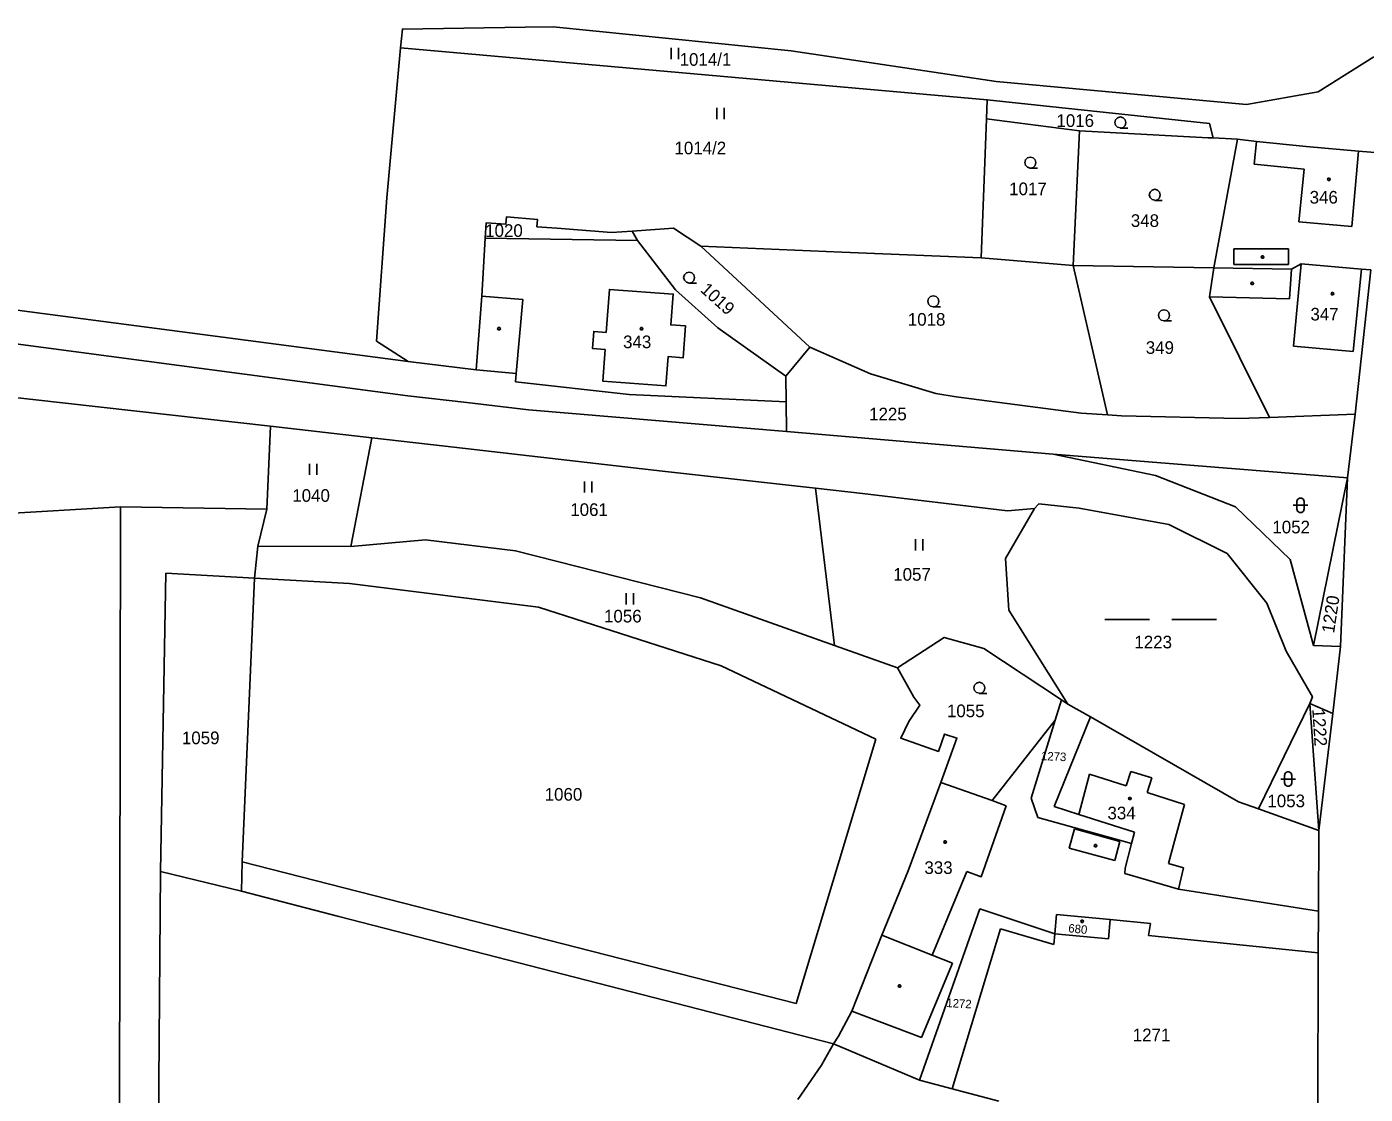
# Model space of a CAD drawing. Extents: x -812394 to -807601, y -1013097 to -1009266.
# Drawn here: x -811185.3 to -811005.4, y -1011291.2 to -1011147.8 of the extents above; entities that cross this region are included whole.
import ezdxf

# ---------------------------------------------------------------- set-up
doc = ezdxf.new("R2010")
doc.units = 0
for name, color, linetype in [('Default', 7, 'Continuous'), ('KN_HRANICE', 7, 'Continuous'), ('KN_KULTURY', 7, 'Continuous'), ('KN_PARCELY', 7, 'Continuous'), ('KN_SLUCKY', 7, 'Continuous')]:
    doc.layers.add(name, color=color, linetype=linetype)

# ---------------------------------------------------------------- blocks, each defined once
blk = doc.blocks.new('304')
at = {"layer": 'Default'}
blk.add_lwpolyline([(0, 0), (-0.38, 0.1), (-0.65, 0.37), (-0.75, 0.74), (-0.65, 1.11), (-0.38, 1.38), (-0.01, 1.48), (0.36, 1.38), (0.63, 1.11), (0.73, 0.73), (0.63, 0.35), (0.36, 0.08), (-0.02, -0.02), (0.98, -0.02)], dxfattribs=at)
blk = doc.blocks.new('306')
at = {"layer": 'Default'}
for p, q in [((-0.5, 1.5), (-0.5, 0)), ((0.5, 0), (0.5, 1.5))]:
    blk.add_line(p, q, dxfattribs=at)
blk = doc.blocks.new('316')
at = {"layer": 'Default'}
for points in [[(-0.5, 1.5), (-0.4, 1.79), (-0.15, 1.97), (0.16, 1.97), (0.41, 1.79), (0.51, 1.5), (0.51, 0.5), (0.41, 0.21), (0.16, 0.03), (-0.15, 0.03), (-0.4, 0.21), (-0.5, 0.5), (-0.5, 1.5)], [(-1, 1), (0.27, 1), (1, 1)]]:
    blk.add_lwpolyline(points, dxfattribs=at)
blk = doc.blocks.new('803')
at = {"layer": 'Default'}
for p, q in [((-7.5, 0), (-1.5, 0)), ((1.5, 0), (7.5, 0))]:
    blk.add_line(p, q, dxfattribs=at)
blk = doc.blocks.new('402')
at = {"layer": 'Default'}
blk.add_lwpolyline([(0.09, 0.15), (0.18, 0), (0.09, -0.15), (-0.09, -0.15), (-0.18, 0), (-0.09, 0.15), (0.09, 0.15)], dxfattribs=at)

msp = doc.modelspace()

# ---------------------------------------------------------------- linework, layer by layer
at = {"layer": 'KN_HRANICE'}
for p, q in [((-811114.53, -1011147.8), (-811118.29, -1011147.86)), ((-811082.55, -1011151.04), (-811114.53, -1011147.8)), ((-811135.05, -1011150.61), (-811056.18, -1011157.62)), ((-811055, -1011155.17), (-811082.55, -1011151.04)), ((-811004.2, -1011151.86), (-811011.7, -1011156.55)), ((-811021.36, -1011158.23), (-811055, -1011155.17)), ((-811011.7, -1011156.55), (-811021.36, -1011158.23)), ((-811056.28, -1011160.19), (-811056.18, -1011157.62)), ((-811056.99, -1011178.87), (-811056.28, -1011160.19)), ((-811056.28, -1011160.19), (-811043.79, -1011161.8)), ((-811043.79, -1011161.8), (-811044.65, -1011179.88)), ((-811026.5, -1011162.71), (-811043.79, -1011161.8)), ((-811025.83, -1011162.74), (-811026.5, -1011162.71)), ((-811022.54, -1011162.91), (-811025.83, -1011162.74)), ((-811022.54, -1011162.91), (-811025.73, -1011180.21)), ((-811020, -1011163.23), (-811022.54, -1011162.91)), ((-811013.31, -1011163.87), (-811020, -1011163.23)), ((-811006.28, -1011164.5), (-811013.31, -1011163.87)), ((-811002.95, -1011164.79), (-811006.28, -1011164.5)), ((-811124.13, -1011184), (-811123.68, -1011176.2)), ((-811123.68, -1011176.2), (-811103.23, -1011176.54)), ((-811103.94, -1011175.27), (-811098.37, -1011174.88)), ((-811103.94, -1011175.27), (-811103.23, -1011176.54)), ((-811098.37, -1011174.88), (-811094.68, -1011177.27)), ((-811080.02, -1011190.85), (-811094.68, -1011177.27)), ((-811056.99, -1011178.87), (-811044.65, -1011179.88)), ((-811044.65, -1011179.88), (-811025.73, -1011180.21)), ((-811044.65, -1011179.88), (-811040.04, -1011199.96)), ((-811015.31, -1011180.39), (-811013.97, -1011179.67)), ((-811005.89, -1011180.37), (-811013.97, -1011179.67)), ((-811025.73, -1011180.21), (-811026.32, -1011184.09)), ((-811025.73, -1011180.21), (-811015.31, -1011180.39)), ((-811006.73, -1011199.88), (-811004.64, -1011180.47)), ((-811005.89, -1011180.37), (-811004.64, -1011180.47)), ((-811134.04, -1011192.78), (-811204.59, -1011183.52)), ((-811124.88, -1011193.92), (-811124.13, -1011184)), ((-811026.32, -1011184.09), (-811018.25, -1011200.3)), ((-811080.02, -1011190.85), (-811083.26, -1011194.74)), ((-811134.04, -1011192.78), (-811124.88, -1011193.92)), ((-811119.51, -1011194.4), (-811124.88, -1011193.92)), ((-811119.59, -1011195.52), (-811119.51, -1011194.4)), ((-811210.26, -1011194.98), (-811152.56, -1011201.49)), ((-811083.26, -1011194.74), (-811083.23, -1011198.18)), ((-811126.17, -1011198.3), (-811117.85, -1011199.26)), ((-811117.85, -1011199.26), (-811083.19, -1011202.2)), ((-811083.23, -1011198.18), (-811083.19, -1011202.2)), ((-811153.06, -1011212.61), (-811152.56, -1011201.49)), ((-811152.56, -1011201.49), (-811138.94, -1011203.04)), ((-811040.04, -1011199.96), (-811038.15, -1011200.07)), ((-811038.15, -1011200.07), (-811022.4, -1011200.45)), ((-811018.25, -1011200.3), (-811022.4, -1011200.45)), ((-811006.73, -1011199.88), (-811018.25, -1011200.3)), ((-811006.73, -1011199.88), (-811007.74, -1011208.42)), ((-811141.76, -1011217.63), (-811138.94, -1011203.04)), ((-811138.94, -1011203.04), (-811129.08, -1011204.17)), ((-811083.19, -1011202.2), (-811047.34, -1011205.25)), ((-811129.08, -1011204.17), (-811099.83, -1011207.51)), ((-811047.34, -1011205.25), (-811007.74, -1011208.42)), ((-811099.83, -1011207.51), (-811079.29, -1011209.81)), ((-811012.31, -1011230.97), (-811007.74, -1011208.42)), ((-811007.74, -1011208.42), (-811008.72, -1011231.09)), ((-811076.71, -1011230.96), (-811079.29, -1011209.81)), ((-811192.07, -1011213.48), (-811172.71, -1011212.32)), ((-811172.71, -1011212.32), (-811172.89, -1011326.55)), ((-811153.06, -1011212.61), (-811172.71, -1011212.32)), ((-811154.23, -1011217.6), (-811153.06, -1011212.61)), ((-811154.72, -1011221.9), (-811154.23, -1011217.6)), ((-811141.76, -1011217.63), (-811154.23, -1011217.6)), ((-811167.33, -1011261.3), (-811166.6, -1011221.24)), ((-811166.6, -1011221.24), (-811154.72, -1011221.9)), ((-811154.72, -1011221.9), (-811156.36, -1011260.04)), ((-811154.72, -1011221.9), (-811141.93, -1011222.61)), ((-811141.93, -1011222.61), (-811116.52, -1011225.79)), ((-811116.52, -1011225.79), (-811091.96, -1011233.67)), ((-811076.71, -1011230.96), (-811068.27, -1011233.96)), ((-811008.72, -1011231.09), (-811012.31, -1011230.97)), ((-811008.72, -1011231.09), (-811009.72, -1011240.09)), ((-811091.96, -1011233.67), (-811071.16, -1011243.55)), ((-811047.07, -1011241), (-811046.22, -1011238.23)), ((-811046.22, -1011238.23), (-811045.35, -1011238.81)), ((-811045.35, -1011238.81), (-811042.32, -1011240.54)), ((-811019.74, -1011252.9), (-811012.81, -1011238.74)), ((-811012.81, -1011238.74), (-811009.72, -1011240.09)), ((-811011.6, -1011255.83), (-811012.81, -1011238.74)), ((-811047.07, -1011241), (-811055.55, -1011251.77)), ((-811050.3, -1011251.47), (-811047.07, -1011241)), ((-811047.2, -1011252.6), (-811042.32, -1011240.54)), ((-811042.32, -1011240.54), (-811022.4, -1011251.94)), ((-811009.72, -1011240.09), (-811011.6, -1011255.83)), ((-811071.16, -1011243.55), (-811081.9, -1011279.06)), ((-811062.44, -1011249.35), (-811066.83, -1011261.23)), ((-811055.55, -1011251.77), (-811062.44, -1011249.35)), ((-811049.38, -1011254.06), (-811050.3, -1011251.47)), ((-811019.74, -1011252.9), (-811022.4, -1011251.94)), ((-811043.88, -1011253.66), (-811047.2, -1011252.6)), ((-811043.88, -1011253.66), (-811036.39, -1011256.05)), ((-811011.6, -1011255.83), (-811019.74, -1011252.9)), ((-811036.79, -1011257.56), (-811049.38, -1011254.06)), ((-811036.39, -1011256.05), (-811036.79, -1011257.56)), ((-811011.67, -1011266.63), (-811011.6, -1011255.83)), ((-811036.79, -1011257.56), (-811037.67, -1011260.89)), ((-811156.36, -1011260.04), (-811156.44, -1011263.96)), ((-811081.9, -1011279.06), (-811156.36, -1011260.04)), ((-811037.7, -1011261.59), (-811037.67, -1011260.89)), ((-811167.89, -1011326.74), (-811167.33, -1011261.3)), ((-811167.33, -1011261.3), (-811156.44, -1011263.96)), ((-811066.83, -1011261.23), (-811070.36, -1011269.87)), ((-811030.48, -1011263.68), (-811037.7, -1011261.59)), ((-811156.44, -1011263.96), (-811143.37, -1011267.37)), ((-811030.48, -1011263.68), (-811011.67, -1011266.63)), ((-811065.28, -1011289.37), (-811057.2, -1011266.35)), ((-811057.2, -1011266.35), (-811047.1, -1011269.68)), ((-811143.37, -1011267.37), (-811076.86, -1011284.5)), ((-811046.86, -1011267.11), (-811047.1, -1011269.68)), ((-811046.86, -1011267.11), (-811039.65, -1011267.75)), ((-811039.65, -1011267.75), (-811039.91, -1011270.38)), ((-811039.65, -1011267.75), (-811034.25, -1011268.29)), ((-811011.7, -1011272.27), (-811011.67, -1011266.63)), ((-811070.36, -1011269.87), (-811074.4, -1011280.09)), ((-811054.41, -1011269.03), (-811060.91, -1011290.53)), ((-811047.26, -1011271.12), (-811054.41, -1011269.03)), ((-811047.1, -1011269.68), (-811047.26, -1011271.12)), ((-811039.91, -1011270.38), (-811047.1, -1011269.68)), ((-811034.25, -1011268.29), (-811034.51, -1011269.93)), ((-811034.51, -1011269.93), (-811011.7, -1011272.27)), ((-811011.7, -1011272.27), (-811011.75, -1011293.77)), ((-811074.4, -1011280.09), (-811076.18, -1011283.43)), ((-811076.18, -1011283.43), (-811076.86, -1011284.5)), ((-811078.49, -1011287.34), (-811076.86, -1011284.5)), ((-811076.86, -1011284.5), (-811065.28, -1011289.37)), ((-811078.49, -1011287.34), (-811081.65, -1011291.97)), ((-811065.28, -1011289.37), (-811060.91, -1011290.53)), ((-811060.91, -1011290.53), (-811054.65, -1011292.2))]:
    msp.add_line(p, q, dxfattribs=at)
for points in [[(-811118.29, -1011147.86), (-811134.82, -1011148.12), (-811135.05, -1011150.61)], [(-811135.05, -1011150.61), (-811136.91, -1011170.79), (-811138.29, -1011190.03), (-811134.04, -1011192.78)], [(-811056.18, -1011157.62), (-811026.31, -1011160.81), (-811025.83, -1011162.74)], [(-811123.68, -1011176.2), (-811123.56, -1011174.16), (-811120.9, -1011174.34), (-811120.82, -1011173.33), (-811116.66, -1011173.68), (-811116.74, -1011174.67), (-811114.06, -1011174.87), (-811106.69, -1011175.46), (-811103.94, -1011175.27)], [(-811103.23, -1011176.54), (-811098.1, -1011183.16), (-811092.39, -1011188.27), (-811083.26, -1011194.74)], [(-811094.68, -1011177.27), (-811075.76, -1011178.11), (-811056.99, -1011178.87)], [(-811126.17, -1011198.3), (-811134.07, -1011197.39), (-811205.09, -1011188), (-811235.6, -1011185.13), (-811253.42, -1011185.08)], [(-811040.04, -1011199.96), (-811043.56, -1011199.74), (-811060.37, -1011197.53), (-811063.11, -1011197.07), (-811071.87, -1011194.45), (-811080.02, -1011190.85)], [(-811083.23, -1011198.18), (-811104.34, -1011197.21), (-811119.59, -1011195.52)], [(-811012.31, -1011230.97), (-811015.45, -1011219.39), (-811022.8, -1011212.32), (-811033.57, -1011208.12), (-811047.34, -1011205.25)], [(-811079.29, -1011209.81), (-811072.96, -1011210.52), (-811053.49, -1011212.84), (-811049.84, -1011212.52)], [(-811049.84, -1011212.52), (-811049.25, -1011211.91), (-811043.85, -1011212.49), (-811031.77, -1011214.67), (-811023.94, -1011218.57), (-811018.6, -1011225.28), (-811016, -1011231.72), (-811012.47, -1011237.86), (-811012.81, -1011238.74)], [(-811045.35, -1011238.81), (-811053.28, -1011226.18), (-811053.74, -1011219.25), (-811049.84, -1011212.52)], [(-811141.76, -1011217.63), (-811131.69, -1011216.74), (-811119.6, -1011218.21), (-811094.76, -1011224.53), (-811076.71, -1011230.96)], [(-811068.27, -1011233.96), (-811061.97, -1011229.86), (-811056.63, -1011231.35), (-811046.22, -1011238.23)], [(-811062.44, -1011249.35), (-811060.27, -1011243.4), (-811061.93, -1011242.85), (-811062.75, -1011245.19), (-811067.83, -1011243.42), (-811066.75, -1011241.18), (-811065.25, -1011238.95), (-811066.04, -1011237.88), (-811068.27, -1011233.96)]]:
    msp.add_lwpolyline(points, dxfattribs=at)
at = {"layer": 'KN_SLUCKY'}
for p, q in [((-811020.31, -1011166.25), (-811020, -1011163.23)), ((-811006.28, -1011164.5), (-811007.17, -1011174.62)), ((-811013.57, -1011166.94), (-811020.31, -1011166.25)), ((-811014.3, -1011174.03), (-811013.57, -1011166.94)), ((-811007.17, -1011174.62), (-811014.3, -1011174.03)), ((-811015.68, -1011177.63), (-811023.04, -1011177.63)), ((-811023.04, -1011177.63), (-811023.04, -1011179.74)), ((-811015.68, -1011179.74), (-811015.68, -1011177.63)), ((-811015.68, -1011179.74), (-811023.04, -1011179.74)), ((-811013.97, -1011179.67), (-811015.01, -1011190.72)), ((-811015.57, -1011184.38), (-811015.31, -1011180.39)), ((-811006.98, -1011191.46), (-811005.89, -1011180.37)), ((-811026.32, -1011184.09), (-811015.57, -1011184.38)), ((-811015.01, -1011190.72), (-811006.98, -1011191.46)), ((-811043.88, -1011253.66), (-811042.43, -1011248.25)), ((-811042.43, -1011248.25), (-811037.52, -1011249.81)), ((-811037.52, -1011249.81), (-811036.9, -1011247.86)), ((-811036.9, -1011247.86), (-811034.06, -1011248.72)), ((-811034.06, -1011248.72), (-811034.7, -1011250.71)), ((-811053.65, -1011252.48), (-811055.55, -1011251.77)), ((-811034.7, -1011250.71), (-811029.67, -1011252.31)), ((-811029.67, -1011252.31), (-811031.16, -1011257.72)), ((-811045.19, -1011258.17), (-811044.48, -1011255.6)), ((-811044.48, -1011255.6), (-811038.35, -1011257.29)), ((-811038.35, -1011257.29), (-811039.06, -1011259.86)), ((-811039.06, -1011259.86), (-811045.19, -1011258.17)), ((-811031.16, -1011257.72), (-811031.84, -1011260.26)), ((-811031.84, -1011260.26), (-811029.8, -1011260.81)), ((-811029.8, -1011260.81), (-811030.48, -1011263.68)), ((-811058.93, -1011261.34), (-811063.58, -1011272.55)), ((-811070.36, -1011269.87), (-811063.58, -1011272.55)), ((-811065.03, -1011283.62), (-811060.86, -1011273.62)), ((-811063.58, -1011272.55), (-811060.86, -1011273.62)), ((-811074.4, -1011280.09), (-811065.03, -1011283.62))]:
    msp.add_line(p, q, dxfattribs=at)
msp.add_lwpolyline([(-811107.44, -1011188.88), (-811109.09, -1011188.75), (-811109.27, -1011191.03), (-811107.56, -1011191.17), (-811107.89, -1011195.41), (-811099.4, -1011196.06), (-811099.09, -1011192.13), (-811097.08, -1011192.29), (-811096.74, -1011188.01), (-811098.74, -1011187.86), (-811098.41, -1011183.73), (-811106.99, -1011183.09)], close=True, dxfattribs=at)
for points in [[(-811124.13, -1011184), (-811118.64, -1011184.45), (-811119.51, -1011194.4)], [(-811053.65, -1011252.48), (-811056.99, -1011262.02), (-811058.93, -1011261.34)]]:
    msp.add_lwpolyline(points, dxfattribs=at)

# ---------------------------------------------------------------- block references
at = {"layer": 'KN_KULTURY'}
for name, p in [('306', (-811098.18, -1011152.15)), ('306', (-811092.05, -1011160.21)), ('304', (-811038.28, -1011161.4)), ('304', (-811050.4, -1011166.78)), ('402', (-811010.26, -1011168.29)), ('304', (-811033.66, -1011171.12)), ('402', (-811019.17, -1011178.74)), ('304', (-811096.26, -1011182.24)), ('402', (-811020.57, -1011182.29)), ('402', (-811009.78, -1011183.68)), ('304', (-811063.44, -1011185.43)), ('304', (-811032.42, -1011187.31)), ('402', (-811121.83, -1011188.38)), ('402', (-811102.67, -1011188.38)), ('306', (-811146.8, -1011208.03)), ('306', (-811109.84, -1011210.39)), ('316', (-811014.08, -1011213.1)), ('306', (-811065.35, -1011218.16)), ('306', (-811104.25, -1011225.42)), ('803', (-811032.89, -1011227.45)), ('304', (-811057.24, -1011237.37)), ('316', (-811015.74, -1011249.9)), ('402', (-811037.02, -1011251.51)), ('402', (-811061.86, -1011257.36)), ('402', (-811041.63, -1011257.85)), ('402', (-811043.45, -1011268.01)), ('402', (-811067.98, -1011276.71))]:
    msp.add_blockref(name, p, dxfattribs=at)

# ---------------------------------------------------------------- texts
at = {"layer": 'KN_PARCELY'}
for s, p in [('1014/1', (-811097.55, -1011153.04)), ('1016', (-811046.89, -1011161.26)), ('1014/2', (-811098.24, -1011164.94)), ('1017', (-811053.25, -1011170.43)), ('346', (-811012.85, -1011171.56)), ('1020', (-811123.69, -1011176.04)), ('348', (-811036.89, -1011174.7)), ('1018', (-811066.87, -1011187.97)), ('347', (-811012.74, -1011187.27)), ('343', (-811105.15, -1011190.99)), ('349', (-811034.88, -1011191.76)), ('1225', (-811072.07, -1011200.69)), ('1040', (-811149.62, -1011211.64)), ('1061', (-811112.25, -1011213.54)), ('1052', (-811017.86, -1011215.88)), ('1057', (-811068.83, -1011222.24)), ('1056', (-811107.71, -1011227.85)), ('1223', (-811036.41, -1011231.33)), ('1055', (-811061.61, -1011240.58)), ('1059', (-811164.46, -1011244.21)), ('1060', (-811115.69, -1011251.8)), ('1053', (-811018.53, -1011252.68)), ('334', (-811040.03, -1011254.31)), ('333', (-811064.64, -1011261.65)), ('1271', (-811036.63, -1011284.13))]:
    msp.add_text(s, height=1.7, dxfattribs=at).set_placement(p)
for s, height, rotation, p in [('1019', 1.7, 318.106, (-811094.88, -1011183.29)), ('1220', 1.7, 81.36, (-811009.57, -1011229.37)), ('1222', 1.7, 273.645, (-811012.5, -1011239.5)), ('1273', 1.14, 357.296, (-811048.98, -1011246.34)), ('680', 1.14, 354.432, (-811045.33, -1011269.48)), ('1272', 1.14, 356.838, (-811061.71, -1011279.53))]:
    msp.add_text(s, height=height, rotation=rotation, dxfattribs=at).set_placement(p)

doc.saveas('drawing.dxf')
